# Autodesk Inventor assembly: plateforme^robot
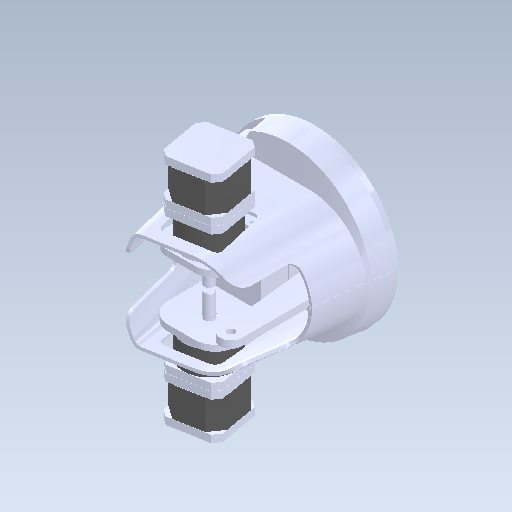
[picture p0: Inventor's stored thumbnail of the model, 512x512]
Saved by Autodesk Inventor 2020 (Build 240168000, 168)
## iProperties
Created: 2018-10
Part Number: plateforme^robot
Document SubType Name: Assembly
Designer: bruno
Mass: 553.596 g
Surface Area: 2077.12 cm^2
Volume: 553.596 cm^3
Density: 1 g/cm^3
Sending System: SolidWorks 2016
Last Author: Prof
Last Saved: 2018-10-31
Author: bruno
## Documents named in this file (11)
- C:\Users\bruno\Documents\Systèmes\Mallette Bras robotisé (273265)\Dossier ressources\Maquette Dobot SW2016\plateforme^robot.iam
- C:\Users\bruno\Documents\Systèmes\Mallette Bras robotisé (273265)\Dossier ressources\Maquette Dobot SW2016\____18_A.ipt
- C:\Users\bruno\Documents\Systèmes\Mallette Bras robotisé (273265)\Dossier ressources\Maquette Dobot SW2016\DIZUO_KE_YOU_A.ipt
- C:\Users\bruno\Documents\Systèmes\Mallette Bras robotisé (273265)\Dossier ressources\Maquette Dobot SW2016\DIZUO_KE_ZUO_A.ipt
- C:\Users\bruno\Documents\Systèmes\Mallette Bras robotisé (273265)\Dossier ressources\Maquette Dobot SW2016\____12_A.ipt
- C:\Users\bruno\Documents\Systèmes\Mallette Bras robotisé (273265)\Dossier ressources\Maquette Dobot SW2016\____11_A.ipt
- C:\Users\bruno\Documents\Systèmes\Mallette Bras robotisé (273265)\Dossier ressources\Maquette Dobot SW2016\____8_A.ipt
- C:\Users\bruno\Documents\Systèmes\Mallette Bras robotisé (273265)\Dossier ressources\Maquette Dobot SW2016\____29_A.ipt
- C:\Users\bruno\Documents\Systèmes\Mallette Bras robotisé (273265)\Dossier ressources\Maquette Dobot SW2016\_____6_A.ipt
- C:\Users\bruno\Documents\Systèmes\Mallette Bras robotisé (273265)\Dossier ressources\Maquette Dobot SW2016\______A.ipt
- C:\Users\bruno\Documents\Systèmes\Mallette Bras robotisé (273265)\Dossier ressources\Maquette Dobot SW2016\_______A.ipt
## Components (11 placed, 10 different names)
1. ____18_A:1
2. ____18_A:2
3. DIZUO_KE_YOU_A:1
4. DIZUO_KE_ZUO_A:1
5. ____12_A:1
6. ____11_A:1
7. ____8_A:1
8. ____29_A:1
9. _____6_A:1
10. ______A:1
11. _______A:1
